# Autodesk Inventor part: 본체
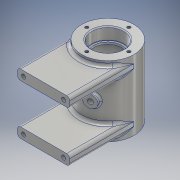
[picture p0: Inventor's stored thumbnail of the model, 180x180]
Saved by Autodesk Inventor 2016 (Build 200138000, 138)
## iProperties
Created: 2020-07
Part Number: 본체
Material: 알루미늄 6061
Document SubType Name: Modeling
Designer: pc-04
Density: 2.7 g/cm^3
Appearance: 알루미늄 - 평지
Mass: 305.352 g
Surface Area: 357.729 cm^2
Volume: 113.093 cm^3
Author: pc-04
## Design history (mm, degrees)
sketch "스케치1"
  geometry: C1 r 26 at (0, 0); 1 further point
  constraints: 1 centre point, 1 coincident
  dimensions: "d0" = 52 diameter of C1
extrude "돌출1" new body sketch "스케치1" stored distance "d1" = 70; taper "d2" = 0 deg
sketch "스케치2"
  geometry: L1 (26, 0)-(26, -64); L2 (26, -64)-(-26, -64); L3 (-26, -64)-(-26, 0); L4 (-26, 0)-(26, 0); A1 r 26 centre (0, 0) between (26, 0) and (-26, 0) reference; 1 further point
  constraints: 8 end point, 2 point on circle, 1 perpendicular, 1 tangent, 1 vertical
  dimensions: "d3" = 64 distance of L1.start L1.end; "d4" = 52 distance of L1.end L2.end; "d5" = 64 distance of L2.end L3.end; "d6" = 52 distance of L3.end L1.start (derived)
extrude "돌출2" join sketch "스케치2" stored distance "d7" = 60; taper "d8" = 0 deg
sketch "스케치3"
  geometry: L1 (60, 0)-(0, 0) reference; L2 (30, 0)-(10, 0); L3 (10, 0)-(10, 64); L4 (10, 64)-(50, 64); L5 (50, 64)-(50, 0); L6 (50, 0)-(30, 0); 1 further point
  constraints: 10 end point, 2 perpendicular, 2 point on line, 1 midpoint
  dimensions: "d9" = 20 distance of L2.start L2.end; "d10" = 64 distance of L2.end L3.end; "d11" = 40 distance of L3.end L4.end; "d12" = 64 distance of L4.end L5.end
extrude "돌출3" cut sketch "스케치3" distance "d13" = 60; taper "d14" = 0 deg
sketch "스케치4"
  geometry: C1 r 26 at (0, 0); 1 further point
  constraints: 1 centre point, 1 coincident
  dimensions: "d15" = 52 diameter of C1
extrude "돌출4" join sketch "스케치4" stored distance "d16" = 70; taper "d17" = 0 deg
sketch "스케치5"
  geometry: L1 (26, 35)-(-26, 35) reference; L2 (0, 35)-(16, 35); L3 (16, 35)-(16, 23); L4 (16, 23)-(14, 23); L5 (0, 0)-(21, 0); L6 (21, 0)-(21, 21); L7 (21, 21)-(14, 21); L8 (14, 21)-(14, 23); L9 (21, 0)-(21, -21); L10 (21, -21)-(14, -21); L11 (14, -21)-(14, -23); L12 (-26, -35)-(26, -35) reference; L13 (0, -35)-(16, -35); L14 (16, -35)-(16, -23); L15 (16, -23)-(14, -23); L16 (0, 35)-(0, -35)
  constraints: 28 end point, 7 perpendicular, 2 midpoint, 2 point on line, 2 vertical, 1 horizontal
  dimensions: "d18" = 16 distance of L2.start L2.end; "d19" = 12 distance of L2.end L3.end; "d20" = 2 distance of L3.end L4.end; "d21" = 21 distance of L5.start L5.end; "d22" = 21 distance of L5.end L6.end; "d23" = 7 distance of L6.end L7.end; "d24" = 2 distance of L7.end L4.end (derived); "d25" = 21 distance of L5.end L9.end; "d26" = 7 distance of L9.end L10.end; "d27" = 2 distance of L10.end L11.end; "d28" = 16 distance of L13.start L13.end; "d29" = 12 distance of L13.end L14.end
revolve "회전1" sketch "스케치5" stored, may be unused: angle "d30" = 90 deg
chamfer "모따기1" distance "d31" = 1; stored, may be unused: second distance "d32" = 2, angle "d33" = 45 deg
fillet "모깎기1" dims "d37" = 3
sketch "스케치6"
  geometry: L1 (0, 0)-(9.919, -27.251); L2 (0, 0)-(0, -64); L3 (26, -64)-(-26, -64) reference; L4 (9.919, -27.251)-(15.557, -25.199); L5 (15.557, -25.199)-(12.992, -18.151); L6 (12.992, -18.151)-(7.353, -20.203)
  constraints: 10 end point, 2 perpendicular, 1 midpoint, 1 point on line
  dimensions: "d38" = 29 distance of L1.start L1.end; "d39" = 20 deg angle of L1 L2; "d40" = 6 distance of L1.end L4.end; "d41" = 7.5 distance of L4.end L5.end
revolve "회전2" sketch "스케치6" stored, may be unused: angle "d42" = 90 deg
sketch "스케치7"
  geometry: 2 further points
  constraints: 1 coincident
hole "구멍1" sketch "스케치7" at (0, 0) diameter "d43" = 4.917; stored, may be unused: countersink angle "d47" = 90 deg, drill point angle "d49" = 118 deg; dims "d44" = 15, "d45" = 4, "d46" = 2, "d48" = 15
sketch "스케치8"
  geometry: A1 r 21 centre (0, 0) between (0, 21) and (-21, 0); 3 further points
  constraints: 4 point on circle, 1 centre point, 1 coincident
  dimensions: "d50" = 42 diameter of A1
hole "구멍2" sketch "스케치8" at (0, 21), (-21, 0), (0, -21), (21, 0) diameter "d51" = 3.242; stored, may be unused: countersink angle "d55" = 90 deg, drill point angle "d57" = 118 deg; dims "d52" = 8, "d53" = 4, "d54" = 2, "d56" = 10
sketch "스케치9"
  geometry: L1 (52, 0)-(0, 0) reference; L2 (26, 0)-(26, -9.948); L3 (26, -4.974)-(6, -4.974); L4 (26, -4.974)-(46, -4.974); L5 (0, -50)-(52, -50) reference; L6 (0, -60)-(52, -60) reference; L7 (26, -50)-(26, -60); L8 (26, -55)-(46, -55); L9 (26, -55)-(6, -55); 5 further points
  constraints: 12 end point, 5 midpoint, 4 coincident, 4 horizontal, 1 vertical
  dimensions: "d58" = 20 distance of L3.start L3.end; "d59" = 20 distance of L3.start L4.end; "d60" = 20 distance of L8.start L8.end; "d61" = 20 distance of L8.start L9.end
hole "구멍3" sketch "스케치9" at (46, -4.974), (6, -4.974), (6, -55), (46, -55) diameter "d62" = 4.134; stored, may be unused: countersink angle "d66" = 90 deg, drill point angle "d68" = 118 deg; dims "d63" = 8, "d64" = 4, "d65" = 2, "d67" = 10
sketch "스케치10"
  geometry: L1 (0, 26)-(0, 29); L2 (0, 29)-(-5, 29); L3 (-5, 29)-(-5, 22); L4 (-5, 22)-(0, 22); L5 (0, 22)-(0, 26); 2 further points
  constraints: 10 end point, 2 perpendicular, 1 point on line, 1 vertical, 1 vertical alignment, 1 other
  dimensions: "d69" = 3 distance of L1.start L1.end; "d70" = 5 distance of L1.end L2.end; "d71" = 7 distance of L2.end L3.end; "d72" = 5 distance of L3.end L4.end
revolve "회전3" sketch "스케치10" stored, may be unused: angle "d73" = 90 deg
sketch "스케치11"
  geometry: 2 further points
  constraints: 1 coincident
hole "구멍4" sketch "스케치11" at (0, 0) diameter "d74" = 4.917; stored, may be unused: countersink angle "d78" = 90 deg, drill point angle "d80" = 118 deg; dims "d75" = 12, "d76" = 4, "d77" = 2, "d79" = 17.1
node "작업 평면2"
sketch "스케치12"
  geometry: L1 (-2.577, -16.46)-(-2.577, 16.723); L2 (-2.577, 16.723)-(2.226, 16.723); L3 (2.226, 16.723)-(2.226, -16.46); L4 (2.226, -16.46)-(-2.577, -16.46); 1 further point
  constraints: 2 other
extrude "돌출5" join sketch "스케치12" stored distance "d82" = 1; taper "d83" = 0 deg
fillet "모깎기3" dims "d84" = 0.3
fillet "모깎기4" dims "d85" = 2
fillet "모깎기5" dims "d86" = 3
fillet "모깎기6" dims "d87" = 3
fillet "모깎기7" dims "d88" = 2
node "솔리드1"
mirror "대칭1"
